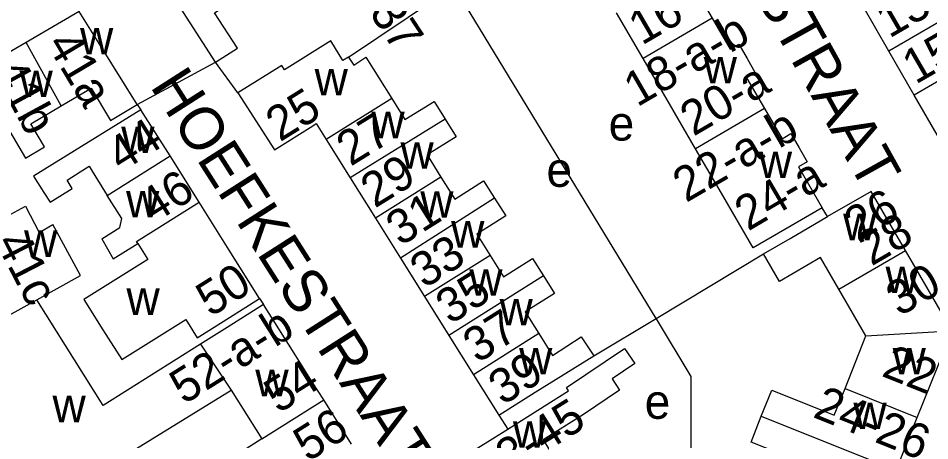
# Model space of a CAD drawing. Extents: x 161141 to 163125, y 381621 to 383200.
# Drawn here: x 162044.8 to 162150.7, y 382509.6 to 382558.7 of the extents above; entities that cross this region are included whole.
import ezdxf

# ---------------------------------------------------------------- set-up
doc = ezdxf.new("R2010")
doc.units = 0
for name, color, linetype in [('BLT_Basislijn', 7, 'Continuous'), ('BLT_Bebouwing', 7, 'Continuous'), ('BLT_Centroide', 7, 'Continuous'), ('BLT_Huisnummer', 7, 'Continuous'), ('BLT_Huisnummer_ tussenligend', 7, 'Continuous'), ('BLT_Huisnummer_reeks', 7, 'Continuous'), ('BLT_Onderverdeling_panden', 7, 'Continuous'), ('BLT_Straatnaam', 7, 'Continuous'), ('BLT_Vlakafsluiter', 7, 'Continuous')]:
    doc.layers.add(name, color=color, linetype=linetype)

msp = doc.modelspace()

# ---------------------------------------------------------------- linework, layer by layer
at = {"layer": 'BLT_Basislijn'}
for p, q in [((162083.15, 382554.17), (162095.42, 382562.41)), ((162118.92, 382523.83), (162095.42, 382562.41)), ((162070.3, 382550.02), (162067.7, 382553.58)), ((162058.6, 382548.67), (162059, 382548.05)), ((162138.85, 382535.65), (162138.23, 382536.68)), ((162118.92, 382523.83), (162131.39, 382531.31)), ((162072.82, 382526.14), (162073.29, 382525.45)), ((162111.66, 382519.48), (162118.92, 382523.83)), ((162100.62, 382512.61), (162101.68, 382510.98))]:
    msp.add_line(p, q, dxfattribs=at)
msp.add_lwpolyline([(162127.15, 382493.43), (162126.68, 382493.65), (162125.02, 382496.08), (162122.79, 382499.9), (162122.98, 382505.75), (162122.98, 382517.07), (162119.07, 382523.59), (162118.92, 382523.83)], dxfattribs=at)
at = {"layer": 'BLT_Bebouwing'}
for p, q in [((162145.97, 382554.88), (162142.93, 382560.13)), ((162117.41, 382554.03), (162114.33, 382559.33)), ((162045.69, 382555.87), (162039.72, 382552.4)), ((162148.93, 382549.77), (162145.97, 382554.88)), ((162120.47, 382548.75), (162117.41, 382554.03)), ((162152.02, 382544.43), (162148.93, 382549.77)), ((162123.5, 382543.54), (162120.47, 382548.75)), ((162062.42, 382542.7), (162059, 382548.05)), ((162080.57, 382544.59), (162083.36, 382540.14)), ((162126.51, 382538.36), (162123.5, 382543.54)), ((162065.78, 382537.34), (162062.42, 382542.7)), ((162083.36, 382540.14), (162086.28, 382535.48)), ((162069.29, 382531.77), (162065.78, 382537.34)), ((162052, 382528.83), (162048.8, 382534.75)), ((162086.28, 382535.48), (162089.2, 382530.84)), ((162054.49, 382533.09), (162055.82, 382530.73)), ((162072.82, 382526.14), (162069.29, 382531.77)), ((162153.32, 382522.38), (162147.89, 382531.71)), ((162089.2, 382530.84), (162092, 382526.36)), ((162143.3, 382521.82), (162140.15, 382527.21)), ((162092, 382526.36), (162094.84, 382521.83)), ((162054.63, 382513.71), (162046.91, 382525.97)), ((162076.85, 382519.8), (162073.29, 382525.45)), ((162149.28, 382512.33), (162153.32, 382522.38)), ((162094.84, 382521.83), (162097.69, 382517.29)), ((162140.89, 382515.7), (162143.3, 382521.82)), ((162078.99, 382516.4), (162076.85, 382519.8)), ((162097.69, 382517.29), (162100.62, 382512.61)), ((162080.28, 382514.36), (162078.99, 382516.4)), ((162047.71, 382502.11), (162069.51, 382515.5)), ((162069.51, 382515.5), (162073.09, 382509.83)), ((162083.5, 382509.24), (162080.28, 382514.36)), ((162146.82, 382506.21), (162149.28, 382512.33)), ((162073.09, 382509.83), (162061.4, 382502.46))]:
    msp.add_line(p, q, dxfattribs=at)
for points in [[(162067.7, 382553.58), (162060.35, 382565.05), (162065.67, 382568.46)], [(162123.38, 382564.51), (162124.33, 382562.85), (162123.34, 382562.28), (162125.43, 382558.68)], [(162067.7, 382553.58), (162070.27, 382555.23), (162067.58, 382559.33), (162070.46, 382561.18)], [(162058.6, 382548.67), (162054.17, 382555.74), (162051.86, 382559.47), (162045.69, 382555.87)], [(162125.43, 382558.68), (162127.51, 382555.09), (162128.52, 382555.67), (162129.49, 382554.01)], [(162081.1, 382556.05), (162075.7, 382552.7), (162075.4, 382553.19), (162070.3, 382550.02)], [(162083.15, 382554.17), (162082.51, 382553.78), (162081.1, 382556.05)], [(162083.15, 382554.17), (162083.79, 382553.23), (162085.18, 382554.16), (162088.18, 382549.37)], [(162129.49, 382554.01), (162130.45, 382552.36), (162129.44, 382551.76), (162131.51, 382548.22)], [(162039.72, 382552.4), (162045.62, 382542.45), (162047.81, 382543.74), (162046.22, 382546.41), (162049.74, 382548.5)], [(162049.74, 382548.5), (162053.25, 382550.58), (162055.49, 382546.82), (162058.6, 382548.67)], [(162070.3, 382550.02), (162074.54, 382543.39), (162079, 382546.21)], [(162088.18, 382549.37), (162089.72, 382546.92), (162093.12, 382549.03), (162094.39, 382546.97)], [(162059, 382548.05), (162046.56, 382540.34), (162047.76, 382538.44), (162048.47, 382537.31), (162051.05, 382538.93), (162050.44, 382539.9), (162051.98, 382540.87), (162053, 382541.51), (162053.36, 382540.92), (162055.12, 382538.12)], [(162131.51, 382548.22), (162133.57, 382544.68), (162134.57, 382545.29), (162135.53, 382543.65)], [(162079, 382546.21), (162079.4, 382546.46), (162080.57, 382544.59)], [(162094.39, 382546.97), (162095.66, 382544.91), (162092.29, 382542.82), (162093.9, 382540.25)], [(162135.53, 382543.65), (162136.49, 382542.01), (162135.47, 382541.42), (162138.23, 382536.68)], [(162093.9, 382540.25), (162095.51, 382537.68), (162098.86, 382539.81), (162100.15, 382537.79)], [(162054.49, 382533.09), (162056.58, 382534.4), (162056.82, 382535.43), (162055.12, 382538.12)], [(162100.15, 382537.79), (162101.43, 382535.76), (162098.06, 382533.62), (162099.61, 382531.13)], [(162138.23, 382536.68), (162133.9, 382534.17), (162130.19, 382532.02), (162126.51, 382538.36)], [(162147.89, 382531.71), (162143.9, 382538.58), (162138.85, 382535.65)], [(162042.15, 382535.02), (162045.63, 382536.86), (162047.2, 382533.82), (162048.8, 382534.75)], [(162131.39, 382531.31), (162134.5, 382533.12), (162138.85, 382535.65)], [(162058.68, 382532.53), (162059.84, 382530.69), (162052.4, 382526.01), (162054.6, 382522.52)], [(162055.82, 382530.73), (162058.68, 382532.53)], [(162099.61, 382531.13), (162101.17, 382528.65), (162104.56, 382530.79), (162105.84, 382528.76)], [(162140.15, 382527.21), (162138.01, 382530.89), (162133.25, 382528.12), (162131.39, 382531.31)], [(162046.91, 382525.97), (162052, 382528.83)], [(162105.84, 382528.76), (162107.11, 382526.74), (162103.71, 382524.59), (162105.3, 382522.06)], [(162054.6, 382522.52), (162056.81, 382519.05), (162064.23, 382523.72), (162065.57, 382521.58), (162068.59, 382523.48), (162072.82, 382526.14)], [(162073.29, 382525.45), (162069.06, 382522.79), (162065.94, 382520.82)], [(162105.3, 382522.06), (162106.89, 382519.52), (162110.2, 382521.68), (162111.66, 382519.48)], [(162065.94, 382520.82), (162054.63, 382513.71)], [(162101.68, 382510.98), (162105.92, 382513.64), (162108.74, 382515.41), (162108.49, 382515.8), (162115.25, 382520.35), (162116.44, 382518.58), (162113.8, 382516.81), (162114.68, 382515.51), (162110.47, 382512.66), (162105.77, 382509.71), (162107.48, 382506.98)], [(162100.62, 382512.61), (162104.87, 382515.25), (162111.66, 382519.48)], [(162131.15, 382512.49), (162132.37, 382515.51), (162139.62, 382512.6), (162140.89, 382515.7)], [(162135.96, 382503.59), (162137.16, 382506.58), (162129.95, 382509.47), (162131.15, 382512.49)], [(162099.91, 382502.24), (162096.46, 382507.71), (162101.68, 382510.98)]]:
    msp.add_lwpolyline(points, dxfattribs=at)
at = {"layer": 'BLT_Onderverdeling_panden'}
for p, q in [((162153.59, 382559.29), (162145.97, 382554.88)), ((162125.43, 382558.68), (162117.41, 382554.03)), ((162161.76, 382557.2), (162148.93, 382549.77)), ((162049.74, 382548.5), (162045.69, 382555.87)), ((162088.18, 382549.37), (162080.57, 382544.59)), ((162131.51, 382548.22), (162123.5, 382543.54)), ((162094.39, 382546.97), (162083.36, 382540.14)), ((162055.12, 382538.12), (162062.42, 382542.7)), ((162093.9, 382540.25), (162086.28, 382535.48)), ((162100.15, 382537.79), (162089.2, 382530.84)), ((162140.15, 382527.21), (162147.89, 382531.71)), ((162099.61, 382531.13), (162092, 382526.36)), ((162105.84, 382528.76), (162094.84, 382521.83)), ((162043.64, 382524.15), (162046.91, 382525.97)), ((162105.3, 382522.06), (162097.69, 382517.29)), ((162143.3, 382521.82), (162153.32, 382522.38)), ((162065.94, 382520.82), (162069.51, 382515.5)), ((162140.89, 382515.7), (162149.28, 382512.33)), ((162073.09, 382509.83), (162080.28, 382514.36)), ((162131.15, 382512.49), (162146.82, 382506.21))]:
    msp.add_line(p, q, dxfattribs=at)
msp.add_lwpolyline([(162058.68, 382532.53), (162058.52, 382532.78), (162065.78, 382537.34)], dxfattribs=at)
at = {"layer": 'BLT_Vlakafsluiter'}
msp.add_line((162058.6, 382548.67), (162067.7, 382553.58), dxfattribs=at)

# ---------------------------------------------------------------- texts
at = {"layer": 'BLT_Centroide'}
for s, p in [('w', (162051.95, 382554.48)), ('w', (162124.45, 382551.11)), ('w', (162044.92, 382549.53)), ('w', (162079.22, 382549.72)), ('w', (162085.82, 382544.75)), ('e', (162113.4, 382544.48)), ('w', (162056.74, 382543.03)), ('w', (162089.2, 382541.22)), ('w', (162130.86, 382540.12)), ('e', (162106.17, 382539.11)), ('w', (162057.3, 382535.56)), ('w', (162091.5, 382535.53)), ('w', (162140.66, 382532.91)), ('w', (162095.09, 382532.06)), ('w', (162045.45, 382530.97)), ('w', (162097.2, 382526.47)), ('w', (162145.59, 382526.78)), ('w', (162057.35, 382524.24)), ('w', (162100.72, 382523.03)), ('w', (162102.99, 382517.34)), ('w', (162146.41, 382517.34)), ('w', (162072.33, 382514.79)), ('w', (162048.75, 382511.78)), ('e', (162117.59, 382512.17)), ('w', (162141.85, 382510.97)), ('w', (162102.28, 382508.81))]:
    msp.add_text(s, height=4, dxfattribs=at).set_placement(p)
at = {"layer": 'BLT_Huisnummer'}
for s, rotation, p in [('41a', 300.6761, (162047.99, 382555.7)), ('41b', 298.5143, (162041.67, 382552.64)), ('25', 31.883, (162075.19, 382544.27)), ('27', 31.7409, (162083.4, 382541.43)), ('44', 32.1323, (162056.74, 382540.76)), ('26', 30.238, (162142.35, 382532.65)), ('31', 32.0784, (162089.19, 382532.15)), ('41c', 297.1832, (162042.09, 382532.66)), ('35', 32.2297, (162094.98, 382523.05)), ('30', 30.1665, (162147.2, 382523.99)), ('39', 31.8754, (162101.08, 382513.67)), ('22', 338.249, (162145, 382517.18)), ('56', 32.1904, (162078.43, 382507.1))]:
    msp.add_text(s, height=4, rotation=rotation, dxfattribs=at).set_placement(p)
at = {"layer": 'BLT_Huisnummer_ tussenligend'}
for s, rotation, p in [('13', 30.0982, (162146.02, 382556.3)), ('29', 31.7409, (162086.22, 382536.57)), ('46', 32.1323, (162060.48, 382534.77)), ('28', 30.238, (162143.95, 382529.85)), ('33', 32.0784, (162091.99, 382527.24)), ('50', 32.181, (162067.11, 382523.92)), ('37', 32.2297, (162098.15, 382518.55))]:
    msp.add_text(s, height=4, rotation=rotation, dxfattribs=at).set_placement(p)
at = {"layer": 'BLT_Huisnummer_reeks'}
for s, rotation, p in [('29 t/m 37', 303.2968, (162076.51, 382573.05)), ('16-a', 30.1452, (162117.26, 382555.49)), ('15-a-b', 30.0733, (162149.08, 382550.95)), ('18-a-b', 30.1452, (162116.71, 382548.32)), ('20-a', 30.28, (162123.26, 382544.92)), ('22-a-b', 30.141, (162122.4, 382537.22)), ('24-a', 30.4075, (162129.61, 382533.91)), ('52-a-b', 32.1848, (162064.04, 382513.77)), ('54', 32.1772, (162075.01, 382512.72)), ('24-26', 338.162, (162137.01, 382512.41)), ('43-45', 32.0523, (162099.41, 382504.11))]:
    msp.add_text(s, height=4, rotation=rotation, dxfattribs=at).set_placement(p)
at = {"layer": 'BLT_Straatnaam'}
for s, rotation, p in [('KETTINGSTRAAT', 299.0957, (162116.25, 382586.74)), ('HOEFKESTRAAT', 302.5607, (162060.02, 382550.8))]:
    msp.add_text(s, height=5, rotation=rotation, dxfattribs=at).set_placement(p)

doc.saveas('drawing.dxf')
